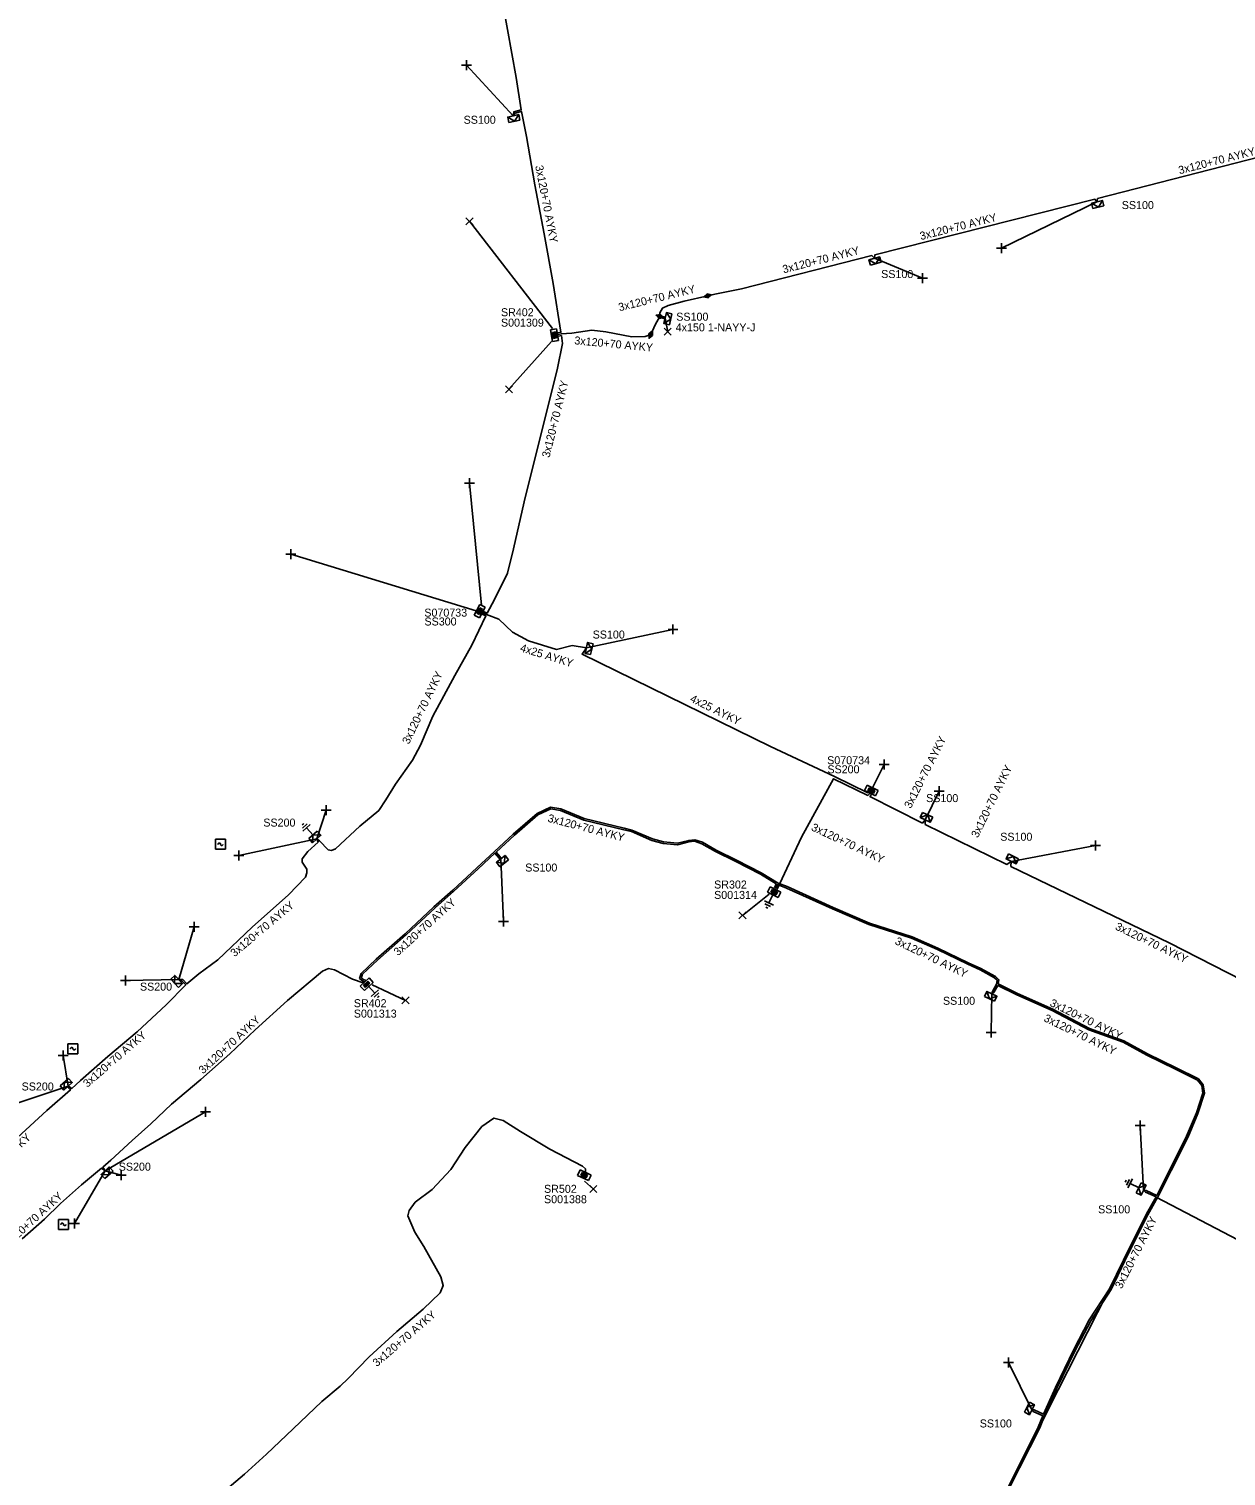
# Model space of a CAD drawing. Extents: x -763093 to -760976, y -1155572 to -1152009.
# Drawn here: x -762444.1 to -762294.5, y -1155041.4 to -1154860.6 of the extents above; entities that cross this region are included whole.
import ezdxf

# ---------------------------------------------------------------- set-up
doc = ezdxf.new("R2010")
doc.units = 0
for name, color, linetype in [('Vrstva 1', 7, 'Continuous'), ('Vrstva 14', 7, 'Continuous'), ('Vrstva 15', 7, 'Continuous'), ('Vrstva 19', 7, 'Continuous'), ('Vrstva 28', 7, 'Continuous'), ('Vrstva 29', 7, 'Continuous'), ('Vrstva 30', 7, 'Continuous'), ('Vrstva 31', 7, 'Continuous'), ('Vrstva 33', 7, 'Continuous'), ('Vrstva 34', 7, 'Continuous'), ('Vrstva 4', 7, 'Continuous'), ('Vrstva 5', 7, 'Continuous'), ('Vrstva 59', 7, 'Continuous'), ('Vrstva 6', 7, 'Continuous'), ('Vrstva 8', 7, 'Continuous'), ('Vrstva 9', 7, 'Continuous')]:
    doc.layers.add(name, color=color, linetype=linetype)

# ---------------------------------------------------------------- blocks, each defined once
blk = doc.blocks.new('NN870')
at = {"layer": 'Vrstva 4'}
for points in [[(0, -0.25), (0.5, 0), (0, 0.25), (-0.5, 0), (0, -0.25)], [(0.37, 0), (0, 0.19), (-0.36, 0), (0, -0.19), (0.37, 0)], [(0.24, 0), (0, 0.12), (-0.25, 0), (0, -0.12), (0.24, 0)], [(0.12, 0), (0, 0.06), (-0.13, 0), (0, -0.06), (0.12, 0)]]:
    blk.add_lwpolyline(points, dxfattribs=at)
blk = doc.blocks.new('NN800')
at = {"layer": 'Vrstva 1'}
for points in [[(-0.44, 0.44), (0.44, -0.44)], [(-0.44, -0.44), (0.44, 0.44)]]:
    blk.add_lwpolyline(points, dxfattribs=at)
blk = doc.blocks.new('NN620')
at = {"layer": 'Vrstva 8'}
for points in [[(0.75, 0), (-0.75, 0)], [(-0.75, 0), (-0.75, -0.75)], [(0.75, -0.75), (0.75, 0)], [(-0.75, -0.75), (0.75, -0.75)], [(0.37, -0.18), (-0.38, -0.18)], [(-0.38, -0.18), (-0.38, -0.56)], [(-0.38, -0.56), (0.37, -0.56)], [(0.32, -0.23), (-0.33, -0.23)], [(-0.33, -0.23), (-0.33, -0.51)], [(-0.33, -0.51), (0.32, -0.51)], [(0.27, -0.27), (-0.28, -0.27)], [(-0.28, -0.27), (-0.28, -0.46)], [(-0.28, -0.46), (0.27, -0.46)], [(0.23, -0.32), (-0.23, -0.32)], [(-0.23, -0.32), (-0.23, -0.42)], [(-0.23, -0.42), (0.23, -0.42)], [(-0.19, -0.37), (0.19, -0.37)], [(0.23, -0.42), (0.23, -0.32)], [(0.27, -0.46), (0.27, -0.27)], [(0.32, -0.51), (0.32, -0.23)], [(0.37, -0.56), (0.37, -0.18)]]:
    blk.add_lwpolyline(points, dxfattribs=at)
blk = doc.blocks.new('NN630')
at = {"layer": 'Vrstva 9'}
for points in [[(0, -0.7), (-0.7, 0)], [(-0.7, -0.7), (-0.7, 0), (0.7, 0), (0.7, -0.7)], [(-0.7, -0.7), (0.7, -0.7)], [(0, -0.7), (0.7, 0)]]:
    blk.add_lwpolyline(points, dxfattribs=at)
blk = doc.blocks.new('NN810')
at = {"layer": 'Vrstva 14'}
for points in [[(0, -0.64), (0, -1.89)], [(0.63, -1.89), (-0.62, -1.89)], [(0.39, -2.2), (-0.4, -2.2)], [(0, -2.52), (-0.12, -2.52)], [(0.14, -2.52), (0, -2.52)]]:
    blk.add_lwpolyline(points, dxfattribs=at)
blk = doc.blocks.new('NN740')
at = {"layer": 'Vrstva 1'}
for points in [[(0.62, 0.62), (-0.63, 0.62)], [(-0.63, 0.62), (-0.63, -0.63)], [(0, 0), (0, 0.01), (0, 0.03), (-0.01, 0.05), (-0.01, 0.06), (-0.02, 0.08), (-0.03, 0.09), (-0.04, 0.1), (-0.05, 0.11), (-0.06, 0.12), (-0.08, 0.13), (-0.09, 0.14), (-0.11, 0.14), (-0.12, 0.15), (-0.14, 0.15), (-0.15, 0.15), (-0.17, 0.15), (-0.18, 0.15), (-0.2, 0.15), (-0.21, 0.14), (-0.23, 0.13), (-0.24, 0.12), (-0.26, 0.11), (-0.27, 0.1), (-0.28, 0.09), (-0.29, 0.08), (-0.29, 0.06), (-0.3, 0.05), (-0.3, 0.03), (-0.31, 0.02), (-0.31, 0), (-0.31, 0)], [(0.62, -0.63), (0.62, 0.62)], [(-0.63, -0.63), (0.62, -0.63)], [(0, 0), (0, -0.02), (0, -0.03), (0.01, -0.05), (0.01, -0.06), (0.02, -0.08), (0.03, -0.09), (0.04, -0.1), (0.05, -0.11), (0.06, -0.12), (0.07, -0.13), (0.09, -0.14), (0.1, -0.15), (0.12, -0.15), (0.13, -0.15), (0.15, -0.15), (0.16, -0.15), (0.18, -0.15), (0.19, -0.15), (0.21, -0.14), (0.22, -0.14), (0.24, -0.13), (0.25, -0.12), (0.26, -0.11), (0.27, -0.09), (0.28, -0.08), (0.29, -0.07), (0.29, -0.05), (0.3, -0.04), (0.3, -0.02), (0.3, -0.01), (0.3, -0.01)]]:
    blk.add_lwpolyline(points, dxfattribs=at)

msp = doc.modelspace()

# ---------------------------------------------------------------- linework, layer by layer
at = {"layer": 'Vrstva 5'}
for points in [[(-762391.76, -1154837.26), (-762391.78, -1154837.11), (-762388.99, -1154836.94), (-762388.5, -1154837.17), (-762388.2, -1154838.15), (-762387.64, -1154841.55), (-762386.55, -1154848.07), (-762385.45, -1154854.42), (-762384.3, -1154860.65), (-762383.22, -1154866.68), (-762382.6, -1154870.72), (-762383.52, -1154870.94), (-762383.6, -1154871.46), (-762383.37, -1154871.11), (-762382.56, -1154870.92), (-762381.92, -1154874.04), (-762380.89, -1154880.07), (-762379.72, -1154886.21), (-762378.6, -1154892.42), (-762377.64, -1154898.51), (-762378.01, -1154898.59)], [(-762359.29, -1154893.96), (-762358.38, -1154893.76), (-762355.07, -1154893.09), (-762338.76, -1154888.92), (-762338.46, -1154889.26), (-762338.41, -1154888.83), (-762310.89, -1154881.88), (-762310.64, -1154882.2), (-762310.56, -1154881.79), (-762273.08, -1154872.18), (-762272.75, -1154872.56), (-762272.68, -1154872.07), (-762257.1, -1154867.81), (-762245.54, -1154873.23), (-762244.31, -1154873.27), (-762238.44, -1154876.17), (-762237.69, -1154877.08), (-762237.69, -1154877.63), (-762237.38, -1154877.32), (-762235.08, -1154878.58), (-762228.32, -1154881.78), (-762227.14, -1154882.16), (-762227.31, -1154882.36)], [(-762365.27, -1154896.53), (-762365.26, -1154896.06), (-762364.95, -1154895.51), (-762364.23, -1154895.17), (-762362.25, -1154894.61), (-762359.29, -1154893.96)], [(-762366.41, -1154898.8), (-762365.8, -1154897.48), (-762365.32, -1154896.62), (-762364.76, -1154896.79), (-762364.6, -1154896.73), (-762364.72, -1154896.59), (-762365.27, -1154896.53)], [(-762387.31, -1154933.39), (-762386.84, -1154933.6), (-762385.92, -1154931.89), (-762384.33, -1154928.59), (-762383.55, -1154925.59), (-762382.23, -1154919.69), (-762380.9, -1154914.32), (-762379.43, -1154908.53), (-762378.06, -1154903.01), (-762377.43, -1154899.92), (-762377.58, -1154898.91), (-762377.95, -1154898.99)], [(-762377.98, -1154898.79), (-762377.61, -1154898.71), (-762376.26, -1154898.62), (-762373.79, -1154898.26), (-762372.01, -1154898.47), (-762368.76, -1154899.08), (-762367.1, -1154899.05), (-762366.41, -1154898.8)], [(-762338.8, -1154956.25), (-762339.01, -1154956.52), (-762332.46, -1154959.85), (-762332.1, -1154959.44), (-762332.11, -1154960.01), (-762321.9, -1154965.01), (-762321.38, -1154964.63), (-762321.4, -1154965.25), (-762301.62, -1154974.8), (-762286.97, -1154982.32), (-762280.33, -1154968.72), (-762280.71, -1154968.39), (-762280.17, -1154968.4), (-762262.87, -1154932.81), (-762263.24, -1154932.33), (-762262.71, -1154932.46), (-762261.78, -1154930.53), (-762260.03, -1154931.06), (-762254.84, -1154933.25), (-762253.57, -1154933.92), (-762253.29, -1154934.1), (-762253.2, -1154934.22)], [(-762387.49, -1154933.75), (-762387.02, -1154933.96), (-762388.76, -1154937.6), (-762390.89, -1154941.38), (-762393.64, -1154946.47), (-762395.18, -1154950.12), (-762396.17, -1154951.97), (-762398.33, -1154954.97), (-762399.52, -1154956.95), (-762400.41, -1154958.26), (-762402.76, -1154960.22), (-762405.82, -1154963.07), (-762406.31, -1154963.26), (-762406.71, -1154963.18), (-762407.83, -1154962.08), (-762408.16, -1154961.83), (-762407.98, -1154962.21), (-762409.28, -1154963.41), (-762409.97, -1154964.31), (-762409.98, -1154964.74), (-762409.38, -1154965.6), (-762409.39, -1154966.08), (-762409.56, -1154966.59), (-762411.69, -1154968.8), (-762416.21, -1154972.85), (-762420.52, -1154976.92), (-762422.91, -1154978.7), (-762424.37, -1154979.94), (-762424.91, -1154979.39), (-762425.41, -1154979.39), (-762425.01, -1154979.57), (-762424.52, -1154980.07), (-762426.96, -1154982.54), (-762430.58, -1154985.92), (-762434.25, -1154989.01), (-762437.66, -1154992.02), (-762438.8, -1154993.04), (-762438.98, -1154992.86), (-762439.23, -1154992.74), (-762439.12, -1154992.99), (-762438.94, -1154993.18), (-762441.88, -1154995.78), (-762445.55, -1154999.12)], [(-762374.46, -1154937.95), (-762376.23, -1154937.67), (-762378.19, -1154938.16), (-762381.68, -1154937.08), (-762383.67, -1154935.98), (-762385.38, -1154934.36), (-762386.93, -1154933.78), (-762387.39, -1154933.58)], [(-762339.24, -1154956.03), (-762339.27, -1154956.06), (-762343.43, -1154954.03), (-762351.43, -1154950.28), (-762374.99, -1154938.72), (-762374.46, -1154937.95)], [(-762350.61, -1154968.1), (-762347.56, -1154961.62), (-762343.56, -1154954.3), (-762339.29, -1154956.38), (-762339.02, -1154956.13)], [(-762402.22, -1154979.67), (-762402.41, -1154979.58), (-762402.8, -1154979.25), (-762402.62, -1154978.62), (-762400.72, -1154976.84), (-762397.11, -1154973.67), (-762393.51, -1154970.31), (-762391.14, -1154968.21), (-762388.14, -1154965.43), (-762385.95, -1154963.41), (-762383.59, -1154961.21), (-762380.62, -1154958.63), (-762378.92, -1154957.87), (-762377.63, -1154958.07), (-762374.73, -1154959.29), (-762369.75, -1154960.48), (-762368.76, -1154960.71), (-762366.21, -1154961.83), (-762364.81, -1154962.2), (-762363.07, -1154962.37), (-762361.67, -1154962), (-762360.91, -1154961.92), (-762359.95, -1154962.24), (-762358.22, -1154963.22), (-762355.71, -1154964.46), (-762352.6, -1154966.05), (-762350.49, -1154967.34), (-762349.35, -1154967.78), (-762343.6, -1154970.39), (-762339.07, -1154972.33), (-762333.75, -1154974.06), (-762330.51, -1154975.48), (-762326.72, -1154977.3), (-762325.15, -1154978.01), (-762323.31, -1154979.01), (-762322.9, -1154979.43), (-762322.97, -1154979.93), (-762320.57, -1154981.12), (-762316.15, -1154983.1), (-762311.58, -1154985.51), (-762307.3, -1154987.05), (-762304.32, -1154988.68), (-762300.75, -1154990.42), (-762297.97, -1154991.81), (-762297.37, -1154992.56), (-762297.2, -1154993.6), (-762298.03, -1154996.14), (-762299.26, -1154999.05), (-762301.35, -1155003.27), (-762303.03, -1155006.56), (-762304.28, -1155008.79), (-762307.16, -1155014.53), (-762308.88, -1155018.13), (-762311.42, -1155022.04), (-762313.39, -1155025.82), (-762315.65, -1155030.45), (-762317.18, -1155033.9), (-762317.8, -1155035.42), (-762320.33, -1155040.42), (-762322.07, -1155043.92)], [(-762402.03, -1154979.53), (-762402.33, -1154979.4), (-762402.58, -1154979.21), (-762402.44, -1154978.72), (-762400.58, -1154976.98), (-762396.97, -1154973.81), (-762393.37, -1154970.45), (-762391, -1154968.35), (-762388, -1154965.57), (-762385.89, -1154963.62), (-762385.37, -1154964.22), (-762385.16, -1154964.31), (-762385.23, -1154964.07), (-762385.74, -1154963.49), (-762383.45, -1154961.35), (-762380.52, -1154958.81), (-762378.9, -1154958.07), (-762377.69, -1154958.27), (-762374.79, -1154959.49), (-762369.79, -1154960.68), (-762368.82, -1154960.91), (-762366.27, -1154962.01), (-762364.85, -1154962.4), (-762363.05, -1154962.57), (-762361.63, -1154962.2), (-762360.93, -1154962.12), (-762360.03, -1154962.42), (-762358.32, -1154963.4), (-762355.79, -1154964.64), (-762352.7, -1154966.23), (-762350.74, -1154967.42), (-762350.96, -1154967.95)], [(-762350.78, -1154968.03), (-762350.57, -1154967.52), (-762349.43, -1154967.96), (-762343.68, -1154970.57), (-762339.15, -1154972.51), (-762333.83, -1154974.24), (-762330.59, -1154975.66), (-762326.8, -1154977.48), (-762325.23, -1154978.19), (-762323.43, -1154979.17), (-762323.12, -1154979.49), (-762323.18, -1154979.98), (-762323.71, -1154980.88), (-762323.77, -1154981.18), (-762323.54, -1154981), (-762323.04, -1154980.12), (-762320.65, -1154981.3), (-762316.23, -1154983.28), (-762311.66, -1154985.69), (-762307.38, -1154987.23), (-762304.42, -1154988.86), (-762300.83, -1154990.6), (-762298.09, -1154991.97), (-762297.55, -1154992.64), (-762297.4, -1154993.58), (-762298.21, -1154996.06), (-762299.44, -1154998.97), (-762301.53, -1155003.19), (-762303.17, -1155006.38), (-762304.51, -1155005.76), (-762304.81, -1155005.73), (-762304.59, -1155005.95), (-762303.26, -1155006.56), (-762304.46, -1155008.69), (-762307.34, -1155014.45), (-762309.06, -1155018.03), (-762311.6, -1155021.94), (-762313.57, -1155025.72), (-762315.83, -1155030.37), (-762317.32, -1155033.73), (-762318.49, -1155033.18), (-762318.77, -1155033.16), (-762318.6, -1155033.36), (-762317.4, -1155033.91), (-762317.98, -1155035.34), (-762320.51, -1155040.34), (-762322.25, -1155043.82)], [(-762444.97, -1155011.79), (-762442.19, -1155009.34), (-762440.16, -1155007.4), (-762437.56, -1155005.03), (-762435.05, -1155002.98), (-762434.6, -1155003.29), (-762434.88, -1155002.86), (-762433.9, -1155001.95), (-762431.22, -1154999.49), (-762428.87, -1154997.41), (-762426.3, -1154994.95), (-762422.63, -1154991.89), (-762419, -1154988.66), (-762415.87, -1154985.68), (-762411.81, -1154982.02), (-762407.42, -1154978.34), (-762406.7, -1154978.03), (-762405.93, -1154978.2), (-762403.69, -1154979.34), (-762402.36, -1154979.82)], [(-762420.19, -1155043.75), (-762417.19, -1155041.2), (-762414.45, -1155038.69), (-762411.12, -1155035.55), (-762407.53, -1155032.14), (-762405.23, -1155030.23), (-762404.21, -1155029.27), (-762401.6, -1155026.55), (-762398.13, -1155023.4), (-762394.86, -1155020.6), (-762392.73, -1155018.53), (-762392.35, -1155017.61), (-762392.65, -1155016.55), (-762394.75, -1155012.75), (-762395.9, -1155010.97), (-762396.77, -1155008.94), (-762396.62, -1155008.24), (-762395.84, -1155007.21), (-762393.73, -1155005.65), (-762391.39, -1155003.14), (-762389.62, -1155000.39), (-762387.52, -1154997.76), (-762386.02, -1154996.71), (-762384.84, -1154996.99), (-762382.69, -1154998.39), (-762379.01, -1155000.59), (-762374.96, -1155002.71), (-762374.58, -1155003.05), (-762374.55, -1155003.52)]]:
    msp.add_lwpolyline(points, dxfattribs=at)
at = {"layer": 'Vrstva 59'}
for points in [[(-762383.6, -1154871.46), (-762389.44, -1154865.13)], [(-762310.64, -1154882.2), (-762322.56, -1154888)], [(-762378.68, -1154898.02), (-762389.06, -1154884.63)], [(-762338.46, -1154889.26), (-762332.44, -1154891.75)], [(-762364.6, -1154896.73), (-762364.29, -1154898.44)], [(-762378.82, -1154899.64), (-762384.13, -1154905.63)], [(-762387.57, -1154932.6), (-762389.06, -1154917.38)], [(-762388.24, -1154933.3), (-762411.38, -1154926.23)], [(-762374.46, -1154937.95), (-762363.63, -1154935.63)], [(-762338.68, -1154955.44), (-762337.24, -1154952.53)], [(-762332.1, -1154959.44), (-762330.36, -1154955.84)], [(-762408.16, -1154961.83), (-762406.96, -1154958.23)], [(-762408.16, -1154961.83), (-762417.88, -1154963.88)], [(-762321.38, -1154964.63), (-762310.81, -1154962.63)], [(-762385.16, -1154964.31), (-762384.81, -1154972.13)], [(-762351.62, -1154968.72), (-762354.94, -1154971.38)], [(-762425.41, -1154979.39), (-762423.46, -1154972.82)], [(-762425.37, -1154979.39), (-762432.06, -1154979.5)], [(-762401.24, -1154980.07), (-762397.06, -1154982)], [(-762323.77, -1154981.18), (-762323.88, -1154986)], [(-762439.23, -1154992.74), (-762439.85, -1154988.87)], [(-762439.23, -1154992.74), (-762454, -1154997.63)], [(-762434.6, -1155003.29), (-762422.04, -1154995.94)], [(-762304.81, -1155005.73), (-762305.25, -1154997.63)], [(-762434.6, -1155003.29), (-762438.44, -1155009.88)], [(-762434.6, -1155003.29), (-762432.61, -1155003.85)], [(-762374.71, -1155004.6), (-762373.57, -1155005.58)], [(-762318.77, -1155033.16), (-762321.69, -1155027.25)]]:
    msp.add_lwpolyline(points, dxfattribs=at)
at = {"layer": 'Vrstva 9'}
msp.add_lwpolyline([(-762395.71, -1155089.89), (-762362.67, -1155098.86), (-762352.24, -1155103.81), (-762329.37, -1155058.32), (-762315.48, -1155030.67), (-762303.23, -1155006.6), (-762286.49, -1155015.33), (-762285.91, -1155014.24), (-762285.73, -1155014.22)], dxfattribs=at)

# ---------------------------------------------------------------- block references
at = {"layer": 'Vrstva 15'}
for p, rotation in [((-762408.16, -1154961.83), -137.68043059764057), ((-762350.82, -1154968.13), -25.95107500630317), ((-762402.15, -1154979.7), 42.10619156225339), ((-762304.81, -1155005.73), -117.10188055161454)]:
    msp.add_blockref('NN810', p, dxfattribs=dict(at, rotation=rotation))
at = {"layer": 'Vrstva 19'}
for p, rotation in [((-762359.29, -1154893.96), 13.980762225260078), ((-762365.27, -1154896.53), -16.62075716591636), ((-762366.41, -1154898.8), 65.1973399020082)]:
    msp.add_blockref('NN870', p, dxfattribs=dict(at, rotation=rotation))
at = {"layer": 'Vrstva 28'}
for p, rotation in [((-762378.07, -1154898.81), -79.99063333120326), ((-762387.47, -1154933.54), -117.59027633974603), ((-762339.01, -1154956.12), 153.76543895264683), ((-762350.82, -1154968.13), -25.97871097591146), ((-762402.15, -1154979.7), 42.10619166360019), ((-762374.55, -1155003.52), -25.831334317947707)]:
    msp.add_blockref('NN620', p, dxfattribs=dict(at, rotation=rotation))
at = {"layer": 'Vrstva 31'}
for p, rotation in [((-762383.6, -1154871.46), 12.720153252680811), ((-762310.64, -1154882.2), 14.218983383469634), ((-762338.46, -1154889.26), 14.438625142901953), ((-762364.6, -1154896.73), 77.24997415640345), ((-762374.46, -1154937.95), 76.62866666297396), ((-762332.1, -1154959.44), 154.18441389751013), ((-762408.16, -1154961.83), -137.68043059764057), ((-762385.16, -1154964.31), 38.61753080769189), ((-762321.38, -1154964.63), 153.7138416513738), ((-762425.41, -1154979.39), -46.41880002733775), ((-762323.77, -1154981.18), -26.17528895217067), ((-762439.23, -1154992.74), -137.8374110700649), ((-762434.6, -1155003.29), 43.020229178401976), ((-762304.81, -1155005.73), -116.8046694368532), ((-762318.77, -1155033.16), -116.72472223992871)]:
    msp.add_blockref('NN630', p, dxfattribs=dict(at, rotation=rotation))
at = {"layer": 'Vrstva 34'}
for p, rotation in [((-762389.44, -1154865.13), 44.99999995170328), ((-762322.56, -1154888), 45), ((-762332.44, -1154891.75), 44.99999995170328), ((-762389.06, -1154917.38), 45), ((-762411.38, -1154926.23), 45), ((-762363.63, -1154935.63), 45), ((-762337.24, -1154952.53), 45), ((-762330.36, -1154955.84), 45), ((-762406.96, -1154958.23), 45), ((-762310.81, -1154962.63), 45), ((-762417.88, -1154963.88), 45), ((-762384.81, -1154972.13), 45), ((-762423.46, -1154972.82), 45), ((-762432.06, -1154979.5), 45), ((-762323.88, -1154986), 45), ((-762439.85, -1154988.87), 45), ((-762422.04, -1154995.94), 45), ((-762305.25, -1154997.63), 45), ((-762432.61, -1155003.85), 45), ((-762438.44, -1155009.88), 44.99999995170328), ((-762321.69, -1155027.25), 44.99999995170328)]:
    msp.add_blockref('NN800', p, dxfattribs=dict(at, rotation=rotation))
for name, p in [('NN800', (-762389.06, -1154884.63)), ('NN800', (-762364.29, -1154898.44)), ('NN800', (-762384.13, -1154905.63)), ('NN740', (-762420.18, -1154962.49)), ('NN800', (-762354.94, -1154971.38)), ('NN800', (-762397.06, -1154982)), ('NN740', (-762438.62, -1154988.04)), ('NN800', (-762373.57, -1155005.58)), ('NN740', (-762439.81, -1155009.99))]:
    msp.add_blockref(name, p, dxfattribs=at)

# ---------------------------------------------------------------- texts
at = {"layer": 'Vrstva 29'}
for s, p in [('S001309', (-762385.13, -1154897.8)), ('S070733', (-762394.71, -1154934.04)), ('S070734', (-762344.36, -1154952.49)), ('S001314', (-762358.49, -1154969.32)), ('S001313', (-762403.52, -1154984.15)), ('S001388', (-762379.75, -1155007.35))]:
    msp.add_text(s, height=1, dxfattribs=at).set_placement(p)
at = {"layer": 'Vrstva 30'}
for s, p in [('SR402', (-762385.13, -1154896.5)), ('SS300', (-762394.69, -1154935.15)), ('SS200', (-762344.33, -1154953.62)), ('SR302', (-762358.49, -1154968.02)), ('SR402', (-762403.52, -1154982.85)), ('SR502', (-762379.75, -1155006.05))]:
    msp.add_text(s, height=1, dxfattribs=at).set_placement(p)
at = {"layer": 'Vrstva 33'}
for s, p in [('SS100', (-762389.8, -1154872.45)), ('SS100', (-762307.54, -1154883.11)), ('SS100', (-762337.61, -1154891.73)), ('SS100', (-762363.22, -1154897.06)), ('SS100', (-762373.67, -1154936.78)), ('SS100', (-762331.99, -1154957.22)), ('SS200', (-762414.83, -1154960.28)), ('SS100', (-762322.73, -1154962.05)), ('SS100', (-762382.1, -1154965.9)), ('SS200', (-762430.25, -1154980.78)), ('SS100', (-762329.89, -1154982.55)), ('SS200', (-762445.04, -1154993.26)), ('SS200', (-762432.9, -1155003.28)), ('SS100', (-762310.5, -1155008.61)), ('SS100', (-762325.29, -1155035.37))]:
    msp.add_text(s, height=1, dxfattribs=at).set_placement(p)
at = {"layer": 'Vrstva 6'}
for s, rotation, p in [('3x120+70 AYKY', 14.396, (-762300.32, -1154878.77)), ('3x120+70 AYKY', 281.036, (-762380.86, -1154877.73)), ('3x120+70 AYKY', 14.176, (-762332.64, -1154886.99)), ('3x120+70 AYKY', 14.342, (-762349.8, -1154891.15)), ('3x120+70 AYKY', 13.833, (-762370.32, -1154895.89)), ('3x120+70 AYKY', 354.66, (-762375.99, -1154900)), ('3x120+70 AYKY', 76.04, (-762379.07, -1154914.24)), ('4x25 AYKY', 342.898, (-762382.82, -1154938.36)), ('3x120+70 AYKY', 64.283, (-762396.64, -1154950.07)), ('4x25 AYKY', 333.873, (-762361.59, -1154944.62)), ('3x120+70 AYKY', 63.068, (-762333.91, -1154958.1)), ('3x120+70 AYKY', 63.933, (-762325.53, -1154961.76)), ('3x120+70 AYKY', 345.317, (-762379.36, -1154959.66)), ('3x120+70 AYKY', 334.77, (-762346.43, -1154960.71)), ('3x120+70 AYKY', 39.971, (-762418.43, -1154976.62)), ('3x120+70 AYKY', 42.104, (-762398, -1154976.49)), ('3x120+70 AYKY', 334.231, (-762308.45, -1154973.1)), ('3x120+70 AYKY', 334.237, (-762335.98, -1154974.92)), ('3x120+70 AYKY', 334.061, (-762316.62, -1154982.65)), ('3x120+70 AYKY', 42.838, (-762422.36, -1154991.25)), ('3x120+70 AYKY', 334.076, (-762317.38, -1154984.55)), ('3x120+70 AYKY', 40.798, (-762436.83, -1154992.94)), ('3x120+70 AYKY', 43.94, (-762450.88, -1155006.07)), ('3x120+70 AYKY', 42.56, (-762447.08, -1155013.25)), ('3x120+70 AYKY', 63.096, (-762307.56, -1155018.12)), ('3x120+70 AYKY', 40.517, (-762400.65, -1155027.84))]:
    msp.add_text(s, height=1, rotation=rotation, dxfattribs=at).set_placement(p)
msp.add_text('4x150 1-NAYY-J', height=1, dxfattribs=at).set_placement((-762363.29, -1154898.39))

doc.saveas('drawing.dxf')
